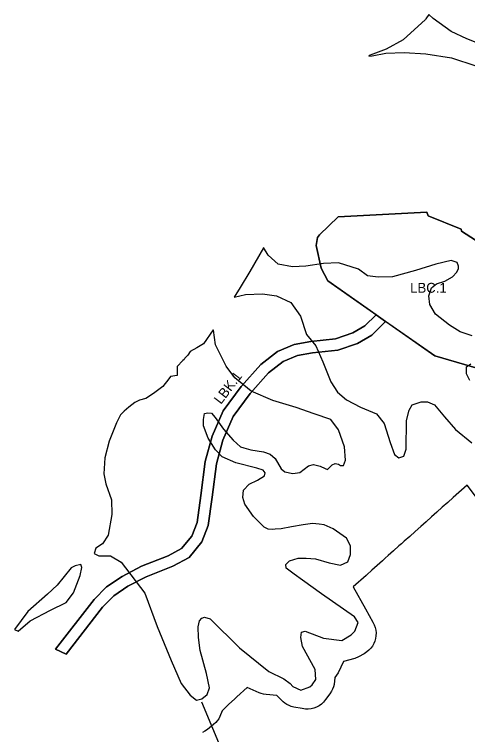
# Model space of a CAD drawing. Extents: x -555426 to -553015, y -1186745 to -1182595.
# Drawn here: x -555343 to -554746, y -1183544 to -1182595 of the extents above; entities that cross this region are included whole.
import ezdxf

# ---------------------------------------------------------------- set-up
doc = ezdxf.new("R2010")
doc.units = 0
for name, color, linetype in [('Level 12', 7, 'Continuous'), ('Level 14', 7, 'Continuous'), ('Level 51', 7, 'Continuous'), ('Level 7', 7, 'Continuous'), ('svahove_deformace', 7, 'Continuous'), ('USES_ID', 7, 'Continuous'), ('USES_LBC_stav', 7, 'Continuous'), ('USES_LBK_stav', 7, 'Continuous')]:
    doc.layers.add(name, color=color, linetype=linetype)

msp = doc.modelspace()

# ---------------------------------------------------------------- linework, layer by layer
at = {"layer": 'Level 12'}
for points in [[(-554866.16, -1182990.72), (-554881.22, -1183005.5), (-554896.86, -1183014.79), (-554919.81, -1183022.59), (-554952.08, -1183026), (-554973.94, -1183030.13), (-554996.15, -1183039.36), (-555018.03, -1183056.32), (-555043.92, -1183085.06), (-555067.48, -1183117.43), (-555082.37, -1183150.81), (-555091.19, -1183184.21), (-555097.03, -1183229.01), (-555101.98, -1183264.57), (-555109.07, -1183282.3), (-555122.43, -1183298.74), (-555140.34, -1183308.43), (-555175.16, -1183322.04), (-555200.86, -1183335.36), (-555221.24, -1183349.19), (-555237.78, -1183365.97), (-555288.38, -1183431.18), (-555274.55, -1183437.81)], [(-555274.55, -1183437.81), (-555226.47, -1183375.87), (-555211.59, -1183360.77), (-555193.17, -1183348.27), (-555168.96, -1183335.72), (-555134.02, -1183322.06), (-555112.67, -1183310.51), (-555095.99, -1183289.99), (-555087.38, -1183268.45), (-555082.16, -1183231.01), (-555076.44, -1183187.1), (-555068.18, -1183155.82), (-555054.42, -1183124.98), (-555032.25, -1183094.52), (-555007.78, -1183067.35), (-554988.54, -1183052.44), (-554969.62, -1183044.58), (-554949.9, -1183040.85), (-554916.57, -1183037.33), (-554890.55, -1183028.49), (-554872, -1183017.47), (-554853.67, -1182999.48)]]:
    msp.add_lwpolyline(points, dxfattribs=at)
at = {"layer": 'Level 14'}
for points in [[(-554660.11, -1182940.98), (-554753.5, -1182880.52), (-554754.24, -1182878), (-554797.61, -1182860.51), (-554799.43, -1182855.5), (-554916.24, -1182861.73), (-554940.94, -1182885.43), (-554943.35, -1182888.88), (-554945.32, -1182899.45), (-554938.75, -1182929.24), (-554929.74, -1182946.1)], [(-554929.74, -1182946.1), (-554788.83, -1183044.98), (-554731.54, -1183061.61)]]:
    msp.add_lwpolyline(points, dxfattribs=at)
at = {"layer": 'Level 51'}
msp.add_lwpolyline([(-555096.26, -1183500.7), (-555050.64, -1183609.84), (-555016.33, -1183690.35), (-554989.42, -1183757.11), (-554981.11, -1183783.33), (-554976.02, -1183820.64), (-554968.52, -1183877.23), (-554966.44, -1183902.87), (-554901.76, -1183903.79), (-554892.29, -1183893.63), (-554839.16, -1183856.09), (-554793.88, -1183825.37), (-554760.96, -1183788.06), (-554748.08, -1183774.08)], dxfattribs=at)
at = {"layer": 'Level 7'}
msp.add_lwpolyline([(-554723.39, -1183245.53), (-554746.22, -1183215.07), (-554764.55, -1183231.55), (-554771.86, -1183238.03), (-554778.94, -1183244.28), (-554785.97, -1183250.6), (-554793.2, -1183257.08), (-554800.42, -1183263.43), (-554807.44, -1183269.75), (-554814.6, -1183276.17), (-554821.83, -1183282.65), (-554829.18, -1183289.15), (-554832.78, -1183292.28), (-554836.1, -1183295.24), (-554843.25, -1183301.71), (-554850.27, -1183307.96), (-554854.04, -1183311.43), (-554857.02, -1183314.17), (-554857.71, -1183314.8), (-554864.82, -1183321.06), (-554871.66, -1183327.13), (-554878.42, -1183333.39), (-554879.34, -1183334.22), (-554896.54, -1183349.19), (-554880.19, -1183378.2), (-554870.4, -1183395.45), (-554868.54, -1183399.24), (-554867.36, -1183402.66), (-554866.59, -1183406.2), (-554866.25, -1183409.8), (-554866.35, -1183413.42), (-554866.89, -1183417), (-554867.86, -1183420.49), (-554869.23, -1183423.83), (-554871.01, -1183426.99), (-554873.15, -1183429.91), (-554875.62, -1183432.55), (-554878.4, -1183434.87), (-554881.88, -1183437.13), (-554889.36, -1183441.29), (-554894.29, -1183443.54), (-554909.2, -1183447.53), (-554916.03, -1183462.17), (-554920.45, -1183468.48), (-554921.58, -1183477.75), (-554922.33, -1183480.85), (-554923.44, -1183483.84), (-554924.88, -1183486.68), (-554927.01, -1183489.88), (-554932.67, -1183497.53), (-554935.49, -1183500.89), (-554938.25, -1183503.44), (-554941.32, -1183505.63), (-554944.63, -1183507.41), (-554948.13, -1183508.77), (-554951.78, -1183509.67), (-554955.52, -1183510.12), (-554959.28, -1183510.09), (-554963.63, -1183509.5), (-554974.39, -1183507.36), (-554977.98, -1183506.46), (-554980.9, -1183505.38), (-554983.68, -1183503.98), (-554986.29, -1183502.3), (-554988.71, -1183500.34), (-554996.81, -1183492.15), (-555011.11, -1183490.88), (-555014.6, -1183490.39), (-555017.55, -1183489.68), (-555020.42, -1183488.69), (-555036.09, -1183481.5), (-555049.51, -1183493.72), (-555052.87, -1183496.88), (-555060.24, -1183503.73), (-555068.87, -1183512.25), (-555072.05, -1183520.04), (-555073.59, -1183522.87), (-555075.44, -1183525.5), (-555077.56, -1183527.92), (-555080.3, -1183530.43), (-555088.16, -1183536.77), (-555091.67, -1183539.25), (-555095.13, -1183541.11)], dxfattribs=at)
at = {"layer": 'svahove_deformace'}
for p, q in [((-554830.68, -1182628.91), (-554853.13, -1182640.85)), ((-555014.68, -1182902.52), (-555032.66, -1182933.68)), ((-555014.44, -1182902.08), (-555014.68, -1182902.52)), ((-555080.84, -1183010.83), (-555093.69, -1183029)), ((-555267.93, -1183323.95), (-555286.46, -1183347.02)), ((-555286.46, -1183347.02), (-555299.11, -1183358.62)), ((-555337.87, -1183407.48), (-555321.81, -1183393.89))]:
    msp.add_line(p, q, dxfattribs=at)
for points in [[(-554419.74, -1182644.94), (-554426.06, -1182643.29), (-554446.03, -1182652), (-554459.79, -1182655.7), (-554480.43, -1182657.29), (-554495.25, -1182657.29), (-554526.47, -1182645.65), (-554550.28, -1182640.89), (-554584.15, -1182631.36), (-554619.6, -1182630.83), (-554647.12, -1182631.89), (-554671.99, -1182636.65), (-554693.16, -1182638.24), (-554708.5, -1182638.24), (-554727.55, -1182635.06), (-554746.6, -1182627.66), (-554767.24, -1182617.6), (-554791.05, -1182600.67), (-554796.68, -1182595.29), (-554800.72, -1182601.14), (-554801.19, -1182601.82), (-554830.68, -1182628.91)], [(-554853.13, -1182640.85), (-554874.23, -1182648.75), (-554875.83, -1182650.22), (-554875.72, -1182650.41), (-554871.49, -1182649.88), (-554853.49, -1182646.18), (-554829.15, -1182645.65), (-554800.58, -1182647.23), (-554766.71, -1182652.53), (-554734.96, -1182663.11)], [(-554739.72, -1183018.71), (-554755.6, -1183013.42), (-554769.36, -1183004.42), (-554787.88, -1182990.14), (-554795.28, -1182977.44), (-554796.87, -1182965.79), (-554793.17, -1182955.21), (-554786.82, -1182949.92), (-554775.71, -1182946.74), (-554765.65, -1182940.92), (-554759.83, -1182934.57), (-554757.71, -1182929.81), (-554757.71, -1182926.64), (-554759.3, -1182921.87), (-554767.24, -1182919.23), (-554787.35, -1182923.99), (-554814.33, -1182932.46), (-554844.5, -1182940.92), (-554863.55, -1182941.45), (-554877.31, -1182939.34), (-554889.48, -1182930.87), (-554915.94, -1182922.4), (-554935.51, -1182923.46), (-554958.8, -1182926.64), (-554976.26, -1182927.69), (-554995.31, -1182923.99), (-555008.54, -1182912.35), (-555014.44, -1182902.08)], [(-555032.66, -1182933.68), (-555045.47, -1182954.8), (-555053.14, -1182967.44), (-555038.17, -1182964.21), (-555015.95, -1182963.15), (-554997.43, -1182965.79), (-554978.38, -1182974.79), (-554965.68, -1182992.78), (-554957.74, -1183016.59), (-554945.57, -1183031.94), (-554936.57, -1183052.58), (-554925.99, -1183079.04), (-554916.99, -1183092.79), (-554905.35, -1183102.85), (-554886.83, -1183112.37), (-554865.66, -1183121.37), (-554855.61, -1183134.07), (-554847.67, -1183158.94), (-554841.85, -1183174.82), (-554836.03, -1183179.05), (-554829.68, -1183176.93), (-554826.51, -1183167.94), (-554825.98, -1183129.84), (-554822.8, -1183116.61), (-554818.57, -1183109.2), (-554806.93, -1183105.49), (-554798.46, -1183105.49), (-554789.46, -1183109.2), (-554776.23, -1183125.07), (-554761.42, -1183142.01), (-554740.25, -1183159.47)], [(-555137.08, -1183072.08), (-555139.24, -1183075.33), (-555147.18, -1183085.39), (-555159.35, -1183094.38), (-555169.41, -1183101.26), (-555177.87, -1183103.38), (-555184.22, -1183106.55), (-555192.16, -1183112.37), (-555197.98, -1183117.67), (-555202.74, -1183122.43), (-555208.04, -1183133.01), (-555218.09, -1183157.35), (-555223.38, -1183179.05), (-555224.97, -1183200.22), (-555222.32, -1183213.44), (-555214.91, -1183234.61), (-555214.39, -1183253.66), (-555219.15, -1183281.18), (-555226.56, -1183292.29), (-555235.55, -1183298.11), (-555237.67, -1183304.99), (-555231.32, -1183308.17), (-555215.97, -1183308.17), (-555202.21, -1183316.63), (-555170.99, -1183357.38), (-555154.59, -1183401.3), (-555136.07, -1183446.28), (-555122.84, -1183476.44), (-555111.2, -1183491.79), (-555102.73, -1183498.14), (-555095.85, -1183496.55), (-555088.97, -1183490.73), (-555085.8, -1183482.26), (-555089.5, -1183463.21), (-555097.97, -1183433.05), (-555100.09, -1183415.59), (-555100.61, -1183401.83), (-555099.03, -1183393.89), (-555095.85, -1183390.19), (-555092.15, -1183389.13), (-555084.74, -1183391.24), (-555046.11, -1183429.34), (-555007.48, -1183460.57), (-554987.9, -1183470.09), (-554979.44, -1183476.44), (-554975.73, -1183480.14), (-554965.45, -1183485.23), (-554953.3, -1183480.69), (-554950.33, -1183478.03), (-554945.57, -1183471.15), (-554946.63, -1183457.92), (-554963.03, -1183427.76), (-554965.15, -1183415.59), (-554964.62, -1183408.71), (-554959.86, -1183407.65), (-554935.51, -1183416.64), (-554911.28, -1183419.94), (-554899, -1183412.41), (-554894.24, -1183407.65), (-554890.01, -1183396.01), (-554894.77, -1183388.6), (-554938.16, -1183358.44), (-554963.03, -1183340.44), (-554974.14, -1183332.51), (-554984.73, -1183324.57), (-554985.26, -1183319.81), (-554980.49, -1183315.04), (-554968.85, -1183311.34), (-554958.27, -1183311.34), (-554946.1, -1183312.4), (-554928.11, -1183317.69), (-554913.29, -1183320.34), (-554903.24, -1183316.1), (-554900.06, -1183306.58), (-554900.06, -1183294.94), (-554905.35, -1183284.88), (-554922.81, -1183272.71), (-554934.46, -1183267.42), (-554941.34, -1183266.36), (-554949.8, -1183265.83), (-554962.5, -1183267.42), (-554977.85, -1183270.07), (-554991.08, -1183272.71), (-554999.01, -1183273.24), (-555002.72, -1183273.77), (-555008.54, -1183273.24), (-555013.83, -1183270.59), (-555019.12, -1183265.3), (-555027.59, -1183256.31), (-555039.23, -1183240.43), (-555041.88, -1183231.44), (-555040.82, -1183221.91), (-555033.41, -1183213.97), (-555022.3, -1183208.68), (-555013.3, -1183202.86), (-555012.24, -1183199.16), (-555014.89, -1183195.45), (-555023.36, -1183192.81), (-555050.87, -1183185.93), (-555068.86, -1183177.99), (-555077.86, -1183168.47), (-555087.39, -1183153.12), (-555093.74, -1183137.24), (-555093.74, -1183128.78), (-555092.15, -1183120.84), (-555087.91, -1183119.78), (-555083.15, -1183120.31), (-555078.39, -1183126.13), (-555067.28, -1183141.48), (-555054.58, -1183155.77), (-555045.05, -1183164.76), (-555040.29, -1183165.82), (-555031.29, -1183168.47), (-555014.36, -1183171.11), (-555005.89, -1183174.29), (-554999.01, -1183180.11), (-554991.08, -1183193.87), (-554986.31, -1183197.57), (-554975.73, -1183199.69), (-554966.74, -1183198.63), (-554955.09, -1183189.63), (-554948.74, -1183188.04), (-554939.75, -1183190.16), (-554933.4, -1183193.34), (-554930.22, -1183194.39), (-554923.87, -1183188.57), (-554920.17, -1183186.46), (-554915.94, -1183187.52), (-554913.29, -1183189.1), (-554909.06, -1183189.1), (-554906.41, -1183182.22), (-554908, -1183164.76), (-554915.94, -1183142.54), (-554925.99, -1183128.78), (-554947.69, -1183121.37), (-554971.5, -1183112.9), (-555002.19, -1183103.91), (-555030.76, -1183091.21), (-555052.46, -1183073.74), (-555063.57, -1183058.4), (-555077.86, -1183030.35), (-555080.51, -1183011.3), (-555080.84, -1183010.83)], [(-555093.69, -1183029), (-555102.43, -1183034.15), (-555111.17, -1183039.31)], [(-555111.17, -1183039.31), (-555114.37, -1183044.11), (-555117.98, -1183047.99), (-555119.21, -1183049.69), (-555121.01, -1183051.24), (-555128.36, -1183059.14), (-555128.31, -1183071)], [(-554742.9, -1183077.45), (-554747.13, -1183068.45), (-554747.13, -1183059.46), (-554741.31, -1183055.22)], [(-555128.31, -1183071), (-555137.08, -1183072.08), (-555137.08, -1183072.08)], [(-555321.81, -1183393.89), (-555295.35, -1183379.6), (-555274.71, -1183369.55), (-555264.66, -1183356.85), (-555256.19, -1183334.09), (-555254.07, -1183323.51), (-555255.13, -1183319.81), (-555262.54, -1183321.39), (-555267.93, -1183323.95)], [(-555299.11, -1183358.62), (-555324.88, -1183381.52), (-555342.75, -1183405.14), (-555337.87, -1183407.48)]]:
    msp.add_lwpolyline(points, dxfattribs=at)
at = {"layer": 'USES_LBC_stav'}
msp.add_line((-554853.67, -1182999.48), (-554853.67, -1182999.48), dxfattribs=at)
for points in [[(-554853.67, -1182999.48), (-554866.16, -1182990.72), (-554929.74, -1182946.1), (-554938.75, -1182929.24), (-554945.32, -1182899.45), (-554943.35, -1182888.88), (-554940.94, -1182885.43), (-554916.24, -1182861.73), (-554799.43, -1182855.5), (-554797.61, -1182860.51), (-554754.24, -1182878), (-554753.5, -1182880.52), (-554660.11, -1182940.98)], [(-554571.89, -1182898.35), (-554548.94, -1182917.58), (-554589.32, -1182960.43), (-554591, -1182963.93), (-554628.05, -1183038.04), (-554659.93, -1183058.83), (-554731.54, -1183061.61), (-554788.83, -1183044.98), (-554853.67, -1182999.48)]]:
    msp.add_lwpolyline(points, dxfattribs=at)
at = {"layer": 'USES_LBK_stav'}
msp.add_line((-554866.16, -1182990.72), (-554853.67, -1182999.48), dxfattribs=at)
for points in [[(-555274.55, -1183437.81), (-555288.38, -1183431.18), (-555237.78, -1183365.97), (-555221.24, -1183349.19), (-555200.86, -1183335.36), (-555175.16, -1183322.04), (-555140.34, -1183308.43), (-555122.43, -1183298.74), (-555109.07, -1183282.3), (-555101.98, -1183264.57), (-555097.03, -1183229.01), (-555091.19, -1183184.21), (-555082.37, -1183150.81), (-555067.48, -1183117.43), (-555043.92, -1183085.06), (-555018.03, -1183056.32), (-554996.15, -1183039.36), (-554973.94, -1183030.13), (-554952.08, -1183026), (-554919.81, -1183022.59), (-554896.86, -1183014.79), (-554881.22, -1183005.5), (-554866.16, -1182990.72)], [(-554853.67, -1182999.48), (-554872, -1183017.47), (-554890.55, -1183028.49), (-554916.57, -1183037.33), (-554949.9, -1183040.85), (-554969.62, -1183044.58), (-554988.54, -1183052.44), (-555007.78, -1183067.35), (-555032.25, -1183094.52), (-555054.42, -1183124.98), (-555068.18, -1183155.82), (-555076.44, -1183187.1), (-555082.16, -1183231.01), (-555087.38, -1183268.45), (-555095.99, -1183289.99), (-555112.67, -1183310.51), (-555134.02, -1183322.06), (-555168.96, -1183335.72), (-555193.17, -1183348.27), (-555211.59, -1183360.77), (-555226.47, -1183375.87), (-555274.55, -1183437.81)]]:
    msp.add_lwpolyline(points, dxfattribs=at)

# ---------------------------------------------------------------- texts
at = {"layer": 'USES_ID'}
msp.add_text('LBC.1', height=13, dxfattribs=at).set_placement((-554821.4, -1182961.78))
msp.add_text('LBK.1', height=13, rotation=52.76764, dxfattribs=at).set_placement((-555070.65, -1183109.58))

doc.saveas('drawing.dxf')
